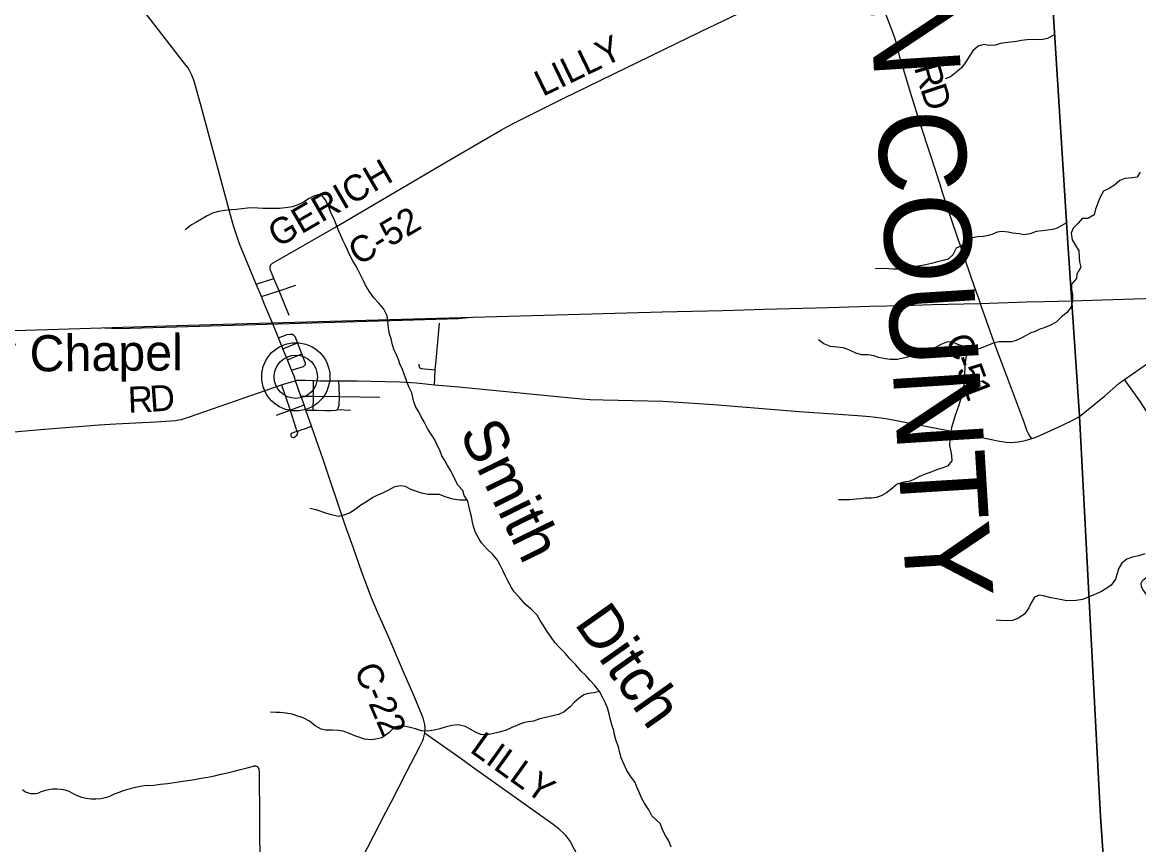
# Model space of a CAD drawing. Extents: x 114604 to 551442, y 316898 to 567001.
# Drawn here: x 123938 to 136809, y 354850 to 364328 of the extents above; entities that cross this region are included whole.
import ezdxf

# ---------------------------------------------------------------- set-up
doc = ezdxf.new("R2010")
doc.units = 0
for name, color, linetype in [('_CIVIL_CONSTRUCTION', 7, 'Continuous'), ('GE_P_Alignment_1000_Bearings', 7, 'Continuous'), ('GE_P_Alignment_1000_Cardinal_Points', 7, 'Continuous'), ('GE_P_Alignment_100_Distances', 7, 'Continuous'), ('GE_P_Alignment_500_Bearings', 7, 'Continuous'), ('GE_P_Alignment_500_Curve_Data', 7, 'Continuous'), ('GE_P_Alignment_500_Distances', 7, 'Continuous'), ('GE_X_Alignment', 7, 'Continuous'), ('PM_P_Cells', 7, 'Continuous'), ('PM_P_CL_Double_Solid', 7, 'Continuous'), ('PM_P_Stop_Line', 7, 'Continuous'), ('PM_X_Dotted_Line', 7, 'Continuous'), ('RS_Raster1', 7, 'Continuous')]:
    doc.layers.add(name, color=color, linetype=linetype)

msp = doc.modelspace()

# ---------------------------------------------------------------- linework, layer by layer
at = {"layer": 'GE_P_Alignment_1000_Bearings'}
for points in [[(136032, 361120), (136634, 361138), (137378, 361159)], [(119614, 360646), (125845, 360836), (129137, 360931), (129546, 360941), (131317, 360990), (132009, 361008), (132259, 361016), (132489, 361021), (133232, 361042), (133708, 361055), (134106, 361066), (134429, 361075), (134976, 361088), (135515, 361105), (135715, 361111), (136032, 361120)], [(124887, 360807), (125042, 360799), (125845, 360823), (128968, 360913), (129114, 360930)]]:
    msp.add_lwpolyline(points, dxfattribs=at)
at = {"layer": 'GE_P_Alignment_1000_Cardinal_Points'}
for p, q in [((126635, 361309), (126839, 361377)), ((126898, 361234), (127090, 361298)), ((127014, 360948), (126898, 361234)), ((128710, 360431), (128749, 360860)), ((126943, 360566), (127111, 360636)), ((127161, 360509), (127111, 360636)), ((126994, 360440), (127161, 360509)), ((128699, 360322), (128710, 360431)), ((128692, 360150), (128699, 360322)), ((126928, 360149), (127025, 359860)), ((127294, 360018), (127296, 360199)), ((127151, 360020), (127294, 360018)), ((127291, 359860), (127294, 360018)), ((127294, 360018), (127594, 360014)), ((127594, 360014), (128059, 360007)), ((126869, 359801), (127025, 359860)), ((127025, 359860), (127187, 359921)), ((127025, 359860), (127103, 359614)), ((127208, 359859), (127291, 359860)), ((127572, 359866), (127721, 359859))]:
    msp.add_line(p, q, dxfattribs=at)
for points in [[(126893, 360690), (126991, 360730), (127022, 360734), (127046, 360734)], [(127111, 360636), (127086, 360699), (127070, 360720), (127046, 360734)], [(127201, 360381), (127203, 360385), (127203, 360396), (127201, 360406), (127161, 360509)], [(127043, 360320), (127182, 360363), (127201, 360381)], [(128510, 360389), (128509, 360371), (128512, 360360), (128517, 360349), (128524, 360344), (128538, 360338), (128699, 360322)], [(127594, 360014), (127595, 360032), (127589, 360198)], [(138845, 355007), (138719, 355176), (138193, 355925), (137521, 356856), (136861, 357787), (136843, 357821), (136839, 357863), (136853, 357895), (136909, 357941), (137656, 358421), (137700, 358457), (137722, 358498), (137729, 358532), (137713, 358576), (137360, 359128), (136829, 359955), (136644, 360213)], [(127572, 359866), (127581, 359883), (127590, 359915), (127594, 360014)], [(127291, 359860), (127335, 359860), (127429, 359854), (127501, 359853), (127556, 359857), (127572, 359866)], [(127115, 359613), (127108, 359582), (127097, 359564), (127083, 359551), (127067, 359540), (127051, 359543), (127046, 359545), (127037, 359560), (127039, 359583), (127045, 359594), (127080, 359609), (127103, 359614)], [(127103, 359614), (127115, 359617), (127154, 359631), (127203, 359645), (127271, 359672)]]:
    msp.add_lwpolyline(points, dxfattribs=at)
at = {"layer": 'GE_P_Alignment_500_Bearings'}
for p, q in [((126839, 361377), (126800, 361473)), ((126694, 361169), (126635, 361309)), ((126898, 361234), (126839, 361377)), ((126694, 361169), (126898, 361234)), ((126943, 360566), (126893, 360690)), ((126994, 360440), (126943, 360566)), ((127043, 360320), (126994, 360440)), ((127208, 359859), (127187, 359921)), ((127271, 359672), (127208, 359859))]:
    msp.add_line(p, q, dxfattribs=at)
for points in [[(126635, 361309), (126443, 361776), (126373, 361984), (126345, 362078), (126006, 363347), (125935, 363597), (125916, 363660), (125893, 363721), (125862, 363779), (125845, 363807), (125825, 363833), (125139, 364723), (124946, 364976), (124875, 365076), (124872, 365080)], [(126800, 361473), (126797, 361493), (126797, 361511), (126801, 361528), (126804, 361533), (126822, 361551), (126829, 361556), (127540, 361963), (128828, 362721), (129086, 362870), (129462, 363091), (129588, 363160), (130175, 363450), (131760, 364224), (132622, 364639), (133302, 364965), (133622, 365116)], [(135577, 359531), (135555, 359557), (135538, 359585), (135524, 359615), (135513, 359646), (135493, 359708), (135295, 360229), (135158, 360597), (134993, 361061), (134970, 361133), (134918, 361278), (134664, 362022), (134549, 362368), (134522, 362458), (134408, 362800), (134286, 363174), (134178, 363518), (134111, 363737), (134057, 363926), (134025, 364053), (133998, 364148), (133953, 364271), (133895, 364424)], [(126893, 360690), (126828, 360854), (126734, 361070), (126694, 361169)], [(136127, 359787), (136414, 360021), (136582, 360167), (136644, 360213), (137529, 360828)], [(127089, 360198), (127071, 360251), (127043, 360320)], [(123127, 359547), (123976, 359619), (124196, 359639), (124825, 359688), (125015, 359700), (125479, 359722), (125708, 359739), (125740, 359745), (125772, 359752), (125866, 359780), (126928, 360149)], [(126928, 360149), (126949, 360156), (127043, 360185), (127089, 360198)], [(127089, 360198), (127106, 360202), (127132, 360203), (127205, 360203), (127296, 360199)], [(127151, 360020), (127123, 360096), (127089, 360198)], [(127296, 360199), (127368, 360198), (127589, 360198)], [(127589, 360198), (127794, 360196), (128285, 360183), (128481, 360172), (128692, 360150)], [(128692, 360150), (128971, 360126), (129363, 360089), (130147, 360010), (130388, 359988), (130484, 359982), (130635, 359976), (131324, 359960), (131498, 359952), (131912, 359923), (132895, 359844), (133570, 359796), (133710, 359785), (133841, 359771), (133938, 359756), (134613, 359623), (135186, 359506), (135282, 359490), (135330, 359487), (135378, 359489), (135419, 359494), (135484, 359505), (135516, 359513), (135577, 359531)], [(127187, 359921), (127169, 359974), (127151, 360020)], [(135577, 359531), (135615, 359544), (135670, 359567), (135879, 359662), (136026, 359733), (136127, 359787)], [(128580, 356139), (128583, 356169), (128583, 356194), (128579, 356234), (128572, 356266), (128563, 356298), (128541, 356359), (128453, 356571), (128334, 356841), (128153, 357263), (128036, 357524), (127963, 357697), (127886, 357897), (127852, 357990), (127757, 358269), (127657, 358545), (127405, 359290), (127271, 359672)], [(126986, 352981), (127009, 353037), (127173, 353359), (127430, 353855), (127712, 354409), (128131, 355226), (128192, 355342), (128371, 355692), (128522, 355983), (128551, 356042), (128563, 356073), (128573, 356104), (128580, 356139)], [(131653, 351455), (131631, 351535), (131556, 351820), (131351, 352577), (131313, 352703), (131278, 352794), (131216, 352926), (131089, 353187), (130643, 354099), (130392, 354620), (130306, 354794), (130262, 354876), (130245, 354904), (130205, 354956), (130171, 354991), (130136, 355023), (130057, 355082), (129129, 355743), (128998, 355838), (128625, 356102), (128599, 356121), (128580, 356139)]]:
    msp.add_lwpolyline(points, dxfattribs=at)
at = {"layer": 'GE_P_Alignment_500_Curve_Data'}
msp.add_line((126683, 354045), (126671, 355703), dxfattribs=at)
for centre, major_axis, ratio, start_param, end_param in [((124781, 359933), (5537, 40), 0.800001, 4.814396, 5.04237), ((126613, 355710), (58.1, 0.4), 0.8, 6.141152, 7.989035), ((124068, 355574), (169, 1), 0.8, 3.836095, 5.185415), ((124319, 355210), (352, 3), 0.8, 0.950623, 2.079405), ((125525, 354648), (1114, 8), 0.8, 1.699011, 2.107814), ((124770, 355716), (423, 3), 0.8, 4.081561, 5.145723)]:
    msp.add_ellipse(centre, major_axis=major_axis, ratio=ratio, start_param=start_param, end_param=end_param, dxfattribs=at)
at = {"layer": 'GE_P_Alignment_500_Distances'}
for points in [[(136712, 350199), (136368, 355174), (136126, 359790), (135994, 361782), (135755, 365552), (135738, 366112), (135422, 370605), (136007, 370979), (136968, 371581), (141444, 374577), (141510, 374219), (141544, 373869), (141529, 373632), (141501, 373414), (141428, 373268), (141184, 372989), (143664, 371810), (146990, 369445), (153829, 364582)], [(114843, 364464), (119922, 364797), (124873, 365078), (133462, 365465), (134430, 365501), (135755, 365552), (135994, 361782), (136126, 359790), (136368, 355174), (136712, 350199)]]:
    msp.add_lwpolyline(points, dxfattribs=at)
at = {"layer": 'GE_X_Alignment'}
for radius in [393, 249]:
    msp.add_circle((127091, 360243), radius, dxfattribs=at)
at = {"layer": 'PM_P_Cells'}
for points in [[(135842, 364186), (135756, 364141), (135704, 364129), (135638, 364127), (135582, 364129), (135524, 364127), (135456, 364119), (135400, 364107), (135332, 364099), (135270, 364091), (135214, 364083), (135160, 364065), (135086, 364061), (135024, 364071), (134958, 364055), (134896, 363999), (134850, 363927), (134810, 363861), (134768, 363805), (134698, 363747), (134640, 363699), (134578, 363677)], [(136826, 362602), (136792, 362542), (136732, 362536), (136650, 362527), (136592, 362507), (136530, 362453), (136460, 362411), (136405, 362382), (136365, 362312), (136341, 362256), (136312, 362176), (136294, 362108), (136222, 362066), (136156, 362068), (136112, 362014), (136055, 361956), (136031, 361898), (136043, 361822), (136075, 361764), (136120, 361696), (136124, 361618), (136128, 361567), (136141, 361507), (136095, 361427), (136093, 361377), (136037, 361315), (136036, 361304)], [(127778, 361531), (127748, 361581), (127710, 361651), (127684, 361713), (127662, 361763), (127634, 361817), (127610, 361871), (127588, 361921), (127562, 361990), (127532, 362058), (127506, 362108), (127484, 362168), (127466, 362220), (127429, 362286), (127381, 362346), (127307, 362330), (127245, 362298), (127179, 362254), (127107, 362220), (127053, 362202), (126971, 362190), (126903, 362182), (126843, 362184), (126769, 362182), (126715, 362182), (126653, 362186), (126585, 362190), (126533, 362188), (126471, 362180), (126405, 362172), (126347, 362168), (126273, 362158), (126201, 362149), (126131, 362129), (126063, 362093), (126005, 362058), (125939, 362020), (125887, 361994), (125817, 361936)], [(135983, 362021), (135870, 361956), (135818, 361940), (135762, 361934), (135700, 361924), (135628, 361916), (135556, 361890), (135486, 361880), (135430, 361890), (135358, 361900), (135306, 361910), (135232, 361916), (135176, 361910), (135126, 361888), (135076, 361872), (135018, 361860), (134954, 361854), (134890, 361844), (134828, 361790), (134758, 361748), (134704, 361726), (134668, 361650), (134614, 361598), (134556, 361584), (134488, 361566), (134436, 361552), (134372, 361536), (134316, 361524), (134262, 361518), (134192, 361504), (134138, 361496), (134088, 361488), (134032, 361484), (133978, 361484), (133924, 361486), (133858, 361490), (133776, 361488)], [(131195, 355181), (131161, 355253), (131117, 355320), (131076, 355392), (131050, 355456), (131028, 355506), (131002, 355566), (130950, 355640), (130908, 355706), (130872, 355782), (130842, 355850), (130824, 355923), (130812, 355979), (130786, 356047), (130766, 356115), (130758, 356167), (130740, 356221), (130720, 356289), (130704, 356357), (130685, 356427), (130663, 356480), (130629, 356550), (130593, 356616), (130539, 356686), (130481, 356748), (130435, 356800), (130383, 356850), (130317, 356926), (130253, 356987), (130195, 357059), (130123, 357131), (130079, 357181), (130029, 357255), (129989, 357309), (129950, 357369), (129910, 357435), (129876, 357495), (129806, 357566), (129736, 357622), (129672, 357700), (129608, 357766), (129580, 357816), (129536, 357890), (129510, 357944), (129482, 358002), (129442, 358081), (129416, 358131), (129362, 358195), (129293, 358261), (129233, 358329), (129201, 358379), (129163, 358449), (129141, 358517), (129127, 358568), (129117, 358632), (129101, 358692), (129085, 358754), (129075, 358808), (129033, 358876), (129017, 358932), (128963, 358990), (128935, 359040), (128873, 359165), (128841, 359221), (128810, 359279), (128776, 359333), (128752, 359397), (128722, 359453), (128690, 359525), (128650, 359587), (128610, 359647), (128572, 359722), (128536, 359782), (128510, 359840), (128476, 359892), (128454, 359954), (128440, 360006), (128428, 360056), (128396, 360126), (128368, 360200), (128341, 360273), (128321, 360325), (128291, 360393), (128275, 360443), (128253, 360497), (128227, 360549), (128207, 360613), (128189, 360679), (128171, 360735), (128161, 360807), (128151, 360878), (128143, 360944), (128103, 361030), (128047, 361090), (127991, 361154), (127945, 361220), (127900, 361290), (127874, 361342), (127842, 361409), (127806, 361479), (127778, 361531)], [(136036, 361304), (136036, 361248), (136045, 361190), (136047, 361126), (136038, 361079)], [(136038, 361079), (136033, 361058), (135983, 360984)], [(135983, 360984), (135921, 360932), (135857, 360872), (135783, 360834), (135721, 360808), (135671, 360790), (135615, 360764), (135565, 360748), (135513, 360720), (135447, 360686), (135395, 360662), (135341, 360646), (135269, 360644), (135199, 360644), (135143, 360636), (135067, 360604), (134993, 360572), (134939, 360556), (134859, 360580), (134805, 360588), (134735, 360612), (134661, 360642), (134605, 360644), (134529, 360616), (134465, 360580), (134411, 360548), (134341, 360524), (134287, 360502), (134229, 360484), (134161, 360472), (134077, 360452), (134023, 360442), (133945, 360442), (133891, 360450), (133811, 360466), (133757, 360484), (133685, 360494), (133619, 360494), (133547, 360514), (133469, 360553), (133401, 360575), (133329, 360585), (133255, 360591), (133179, 360623), (133116, 360667)], [(134867, 360577), (134821, 360486), (134809, 360404), (134805, 360348), (134801, 360271), (134797, 360191), (134791, 360123), (134779, 360057), (134758, 359991), (134736, 359917), (134718, 359861), (134690, 359787), (134674, 359731), (134652, 359657), (134640, 359590), (134630, 359520), (134628, 359450), (134642, 359380), (134650, 359330), (134654, 359274), (134606, 359212), (134538, 359188), (134478, 359170), (134406, 359140), (134348, 359120), (134274, 359090), (134224, 359064), (134174, 359040), (134100, 359028), (134026, 359004), (133950, 358944), (133900, 358906), (133840, 358872), (133782, 358852), (133728, 358844), (133656, 358842), (133604, 358838), (133550, 358832), (133474, 358824), (133350, 358824)], [(129067, 358821), (128981, 358822), (128901, 358832), (128813, 358860), (128749, 358888), (128693, 358888), (128619, 358886), (128539, 358902), (128465, 358930), (128411, 358948), (128357, 358977), (128297, 358987), (128229, 358973), (128159, 358937), (128085, 358899), (128035, 358879), (127981, 358851), (127907, 358802), (127841, 358762), (127775, 358712), (127709, 358670), (127647, 358648), (127583, 358634), (127503, 358652), (127437, 358672), (127325, 358709), (127255, 358723)], [(136881, 358204), (136809, 358180), (136739, 358162), (136673, 358141), (136614, 358093), (136580, 358039), (136558, 357963), (136540, 357911), (136493, 357841), (136441, 357805), (136371, 357763), (136229, 357703)], [(135979, 357661), (135864, 357683), (135796, 357695), (135728, 357713), (135662, 357725), (135606, 357701), (135564, 357631), (135542, 357579), (135498, 357511), (135424, 357459), (135354, 357433), (135288, 357429), (135218, 357433), (135164, 357437)], [(136229, 357703), (136162, 357675), (136090, 357663), (135979, 357661)], [(130592, 356617), (130531, 356600), (130463, 356594), (130411, 356576), (130357, 356538), (130305, 356492), (130255, 356440), (130187, 356380), (130121, 356352), (130041, 356330), (129973, 356316), (129903, 356300), (129831, 356274), (129769, 356266), (129713, 356254), (129647, 356226), (129581, 356200), (129509, 356166), (129435, 356148), (129357, 356126), (129299, 356116), (129223, 356120), (129169, 356144), (129103, 356182), (129049, 356212), (128963, 356232), (128889, 356224), (128815, 356206), (128753, 356186), (128685, 356170), (128609, 356160), (128539, 356164), (128471, 356186), (128409, 356202), (128337, 356218), (128279, 356218), (128229, 356204), (128163, 356138), (128085, 356082), (128015, 356066), (127961, 356060), (127885, 356066), (127829, 356084), (127771, 356104), (127719, 356126), (127637, 356158), (127585, 356165), (127515, 356171), (127439, 356169), (127385, 356181), (127315, 356219), (127251, 356275), (127177, 356313), (127103, 356337), (127051, 356353), (126976, 356365), (126912, 356373), (126860, 356373), (126798, 356379)], [(131418, 354823), (131392, 354893), (131348, 354959), (131318, 355027), (131292, 355095), (131195, 355181)]]:
    msp.add_lwpolyline(points, dxfattribs=at)
at = {"layer": 'PM_X_Dotted_Line'}
msp.add_line((127091, 360243), (127091, 360243), dxfattribs=at)
at = {"layer": 'RS_Raster1'}
for points in [[(141444, 374577), (136968, 371581), (136007, 370979), (135422, 370605), (135738, 366112), (135755, 365552), (135994, 361782), (136126, 359790), (136368, 355174), (136712, 350199)], [(136712, 350199), (136368, 355174), (136126, 359790), (135994, 361782), (135755, 365552), (135738, 366112), (135422, 370605), (136007, 370979), (136968, 371581), (141444, 374577)]]:
    msp.add_lwpolyline(points, dxfattribs=at)

# ---------------------------------------------------------------- texts
at = {"layer": '_CIVIL_CONSTRUCTION'}
msp.add_text('Lilly Chapel', height=417.03, rotation=0.4115, dxfattribs=at).set_placement((122908, 360296))
at = {"layer": 'GE_P_Alignment_100_Distances'}
msp.add_text('MADISON COUNTY', height=1000.06, rotation=273.5639, dxfattribs=at).set_placement((133376, 369893))
at = {"layer": 'PM_P_CL_Double_Solid'}
for s, rotation, p in [('LILLY', 25.8554, (129938, 363468)), ('R', 286.0649, (134217, 363809)), ('D', 288.2483, (134289, 363561)), ('GERICH', 30.0878, (126884, 361726)), ('C-52', 30.6677, (127813, 361518)), ('C', 289.944, (134578, 360676)), ('5', 290.0946, (134704, 360328)), ('-', 289.9787, (134662, 360444)), ('R', 2.2502, (125161, 359828)), ('D', 4.1488, (125418, 359838)), ('1', 290.7521, (134769, 360151)), ('C-22', 293.3462, (127758, 356869)), ('LILLY', 324.3496, (129085, 355926))]:
    msp.add_text(s, height=300, rotation=rotation, dxfattribs=at).set_placement(p)
at = {"layer": 'PM_P_Stop_Line'}
for s, rotation, p in [('Smith', 296.1551, (128971, 359599)), ('Ditch', 305.2056, (130294, 357398))]:
    msp.add_text(s, height=500, rotation=rotation, dxfattribs=at).set_placement(p)

doc.saveas('drawing.dxf')
